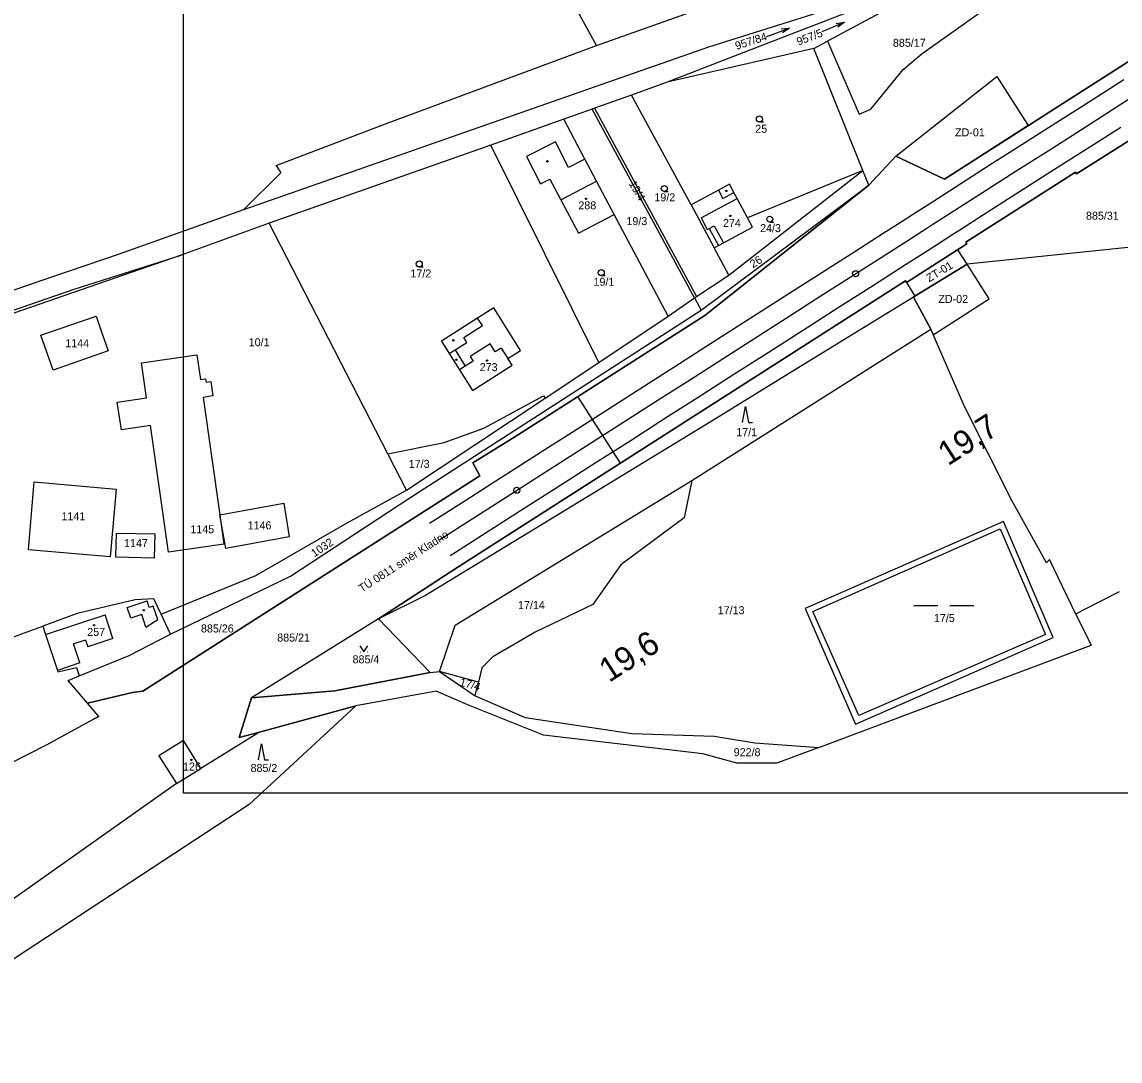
# Model space of a CAD drawing. Extents: x -752184 to -751416, y -1028299 to -1027836.
# Drawn here: x -751921.2 to -751646.8, y -1028255.6 to -1027995.9 of the extents above; entities that cross this region are included whole.
import ezdxf

# ---------------------------------------------------------------- set-up
doc = ezdxf.new("R2010")
doc.units = 0
for name, color, linetype in [('02_Osa_koleje', 7, 'Continuous'), ('03_Staničení', 7, 'Continuous'), ('Dočasné zábory', 7, 'Continuous'), ('Dočasné zábory - čísla', 7, 'Continuous'), ('Pozemky ČD', 7, 'Continuous'), ('Trvalé zábory', 7, 'Continuous'), ('Trvalé zábory - čísla', 7, 'Continuous'), ('Vrstva 4', 7, 'Continuous'), ('Vrstva 53', 7, 'Continuous'), ('Vrstva 55', 7, 'Continuous'), ('Vrstva 56', 7, 'Continuous'), ('Vrstva 57', 7, 'Continuous'), ('Vrstva 58', 7, 'Continuous'), ('Vrstva 59', 7, 'Continuous')]:
    doc.layers.add(name, color=color, linetype=linetype)

msp = doc.modelspace()

# ---------------------------------------------------------------- linework, layer by layer
at = {"layer": '02_Osa_koleje'}
for p, q in [((-751653.82, -1028015.29), (-751645.91, -1028010.23)), ((-751648.69, -1028017.73), (-751640.92, -1028012.76)), ((-751662.87, -1028021.07), (-751653.82, -1028015.29)), ((-751656.74, -1028022.88), (-751648.69, -1028017.73)), ((-751671.32, -1028026.46), (-751662.87, -1028021.07)), ((-751664.8, -1028028.03), (-751656.74, -1028022.88)), ((-751655.05, -1028027.47), (-751646.64, -1028022.11)), ((-751679.23, -1028031.51), (-751671.32, -1028026.46)), ((-751663.19, -1028032.68), (-751655.05, -1028027.47)), ((-751673, -1028033.27), (-751664.8, -1028028.03)), ((-751686.59, -1028036.23), (-751679.23, -1028031.51)), ((-751671.92, -1028038.25), (-751663.19, -1028032.68)), ((-751681.21, -1028038.52), (-751673, -1028033.27)), ((-751693.69, -1028040.78), (-751686.59, -1028036.23)), ((-751688.98, -1028043.49), (-751681.21, -1028038.52)), ((-751680.91, -1028044.01), (-751671.92, -1028038.25)), ((-751697.47, -1028043.2), (-751693.69, -1028040.78)), ((-751702.42, -1028046.37), (-751697.47, -1028043.2)), ((-751691.1, -1028044.85), (-751688.98, -1028043.49)), ((-751686.82, -1028047.78), (-751680.91, -1028044.01)), ((-751705.97, -1028048.65), (-751702.42, -1028046.37)), ((-751695.1, -1028047.41), (-751693.57, -1028046.42)), ((-751693.57, -1028046.42), (-751691.1, -1028044.85)), ((-751713.11, -1028053.22), (-751705.97, -1028048.65)), ((-751699.61, -1028050.29), (-751697.44, -1028048.9)), ((-751697.44, -1028048.9), (-751695.1, -1028047.41)), ((-751692.69, -1028051.52), (-751688.81, -1028049.05)), ((-751688.81, -1028049.05), (-751686.82, -1028047.78)), ((-751707.41, -1028055.27), (-751699.61, -1028050.29)), ((-751696.88, -1028054.2), (-751692.69, -1028051.52)), ((-751722.23, -1028059.04), (-751713.11, -1028053.22)), ((-751700.46, -1028056.5), (-751696.88, -1028054.2)), ((-751715.15, -1028060.22), (-751707.41, -1028055.27)), ((-751708.45, -1028061.62), (-751700.46, -1028056.5)), ((-751731.44, -1028064.93), (-751722.23, -1028059.04)), ((-751722.91, -1028065.18), (-751715.15, -1028060.22)), ((-751717.26, -1028067.26), (-751708.45, -1028061.62)), ((-751740.37, -1028070.64), (-751731.44, -1028064.93)), ((-751730.24, -1028069.87), (-751722.91, -1028065.18)), ((-751726.12, -1028072.93), (-751717.26, -1028067.26)), ((-751749.1, -1028076.23), (-751740.37, -1028070.64)), ((-751738.35, -1028075.06), (-751730.24, -1028069.87)), ((-751734.76, -1028078.44), (-751726.12, -1028072.93)), ((-751758.04, -1028081.94), (-751749.1, -1028076.23)), ((-751746.01, -1028079.96), (-751738.35, -1028075.06)), ((-751743.32, -1028083.91), (-751734.76, -1028078.44)), ((-751767.69, -1028088.11), (-751758.04, -1028081.94)), ((-751754.17, -1028085.18), (-751746.01, -1028079.96)), ((-751762.21, -1028090.32), (-751754.17, -1028085.18)), ((-751752.24, -1028089.62), (-751743.32, -1028083.91)), ((-751776.82, -1028093.96), (-751767.69, -1028088.11)), ((-751769.91, -1028095.24), (-751762.21, -1028090.32)), ((-751759.86, -1028094.49), (-751752.24, -1028089.62)), ((-751785.51, -1028099.52), (-751776.82, -1028093.96)), ((-751777.26, -1028099.94), (-751769.91, -1028095.24)), ((-751769.24, -1028100.51), (-751759.86, -1028094.49)), ((-751795.35, -1028105.81), (-751788.71, -1028101.56)), ((-751788.71, -1028101.56), (-751785.51, -1028099.52)), ((-751785.09, -1028104.95), (-751777.26, -1028099.94)), ((-751777.92, -1028106.05), (-751769.24, -1028100.51)), ((-751803.67, -1028111.13), (-751796.99, -1028106.86)), ((-751796.99, -1028106.86), (-751795.35, -1028105.81)), ((-751793.41, -1028110.27), (-751785.09, -1028104.95)), ((-751787.91, -1028112.43), (-751777.92, -1028106.05)), ((-751807.69, -1028113.7), (-751803.67, -1028111.13)), ((-751801.11, -1028115.2), (-751793.41, -1028110.27)), ((-751797.49, -1028118.58), (-751787.91, -1028112.43)), ((-751818.04, -1028120.32), (-751810.27, -1028115.34)), ((-751810.27, -1028115.35), (-751807.69, -1028113.7)), ((-751808.72, -1028120.07), (-751801.11, -1028115.2)), ((-751819.33, -1028121.15), (-751818.04, -1028120.32)), ((-751816.72, -1028125.18), (-751808.72, -1028120.07)), ((-751806.31, -1028124.21), (-751797.49, -1028118.58)), ((-751816.74, -1028125.19), (-751816.72, -1028125.18)), ((-751812.84, -1028128.4), (-751806.31, -1028124.21)), ((-751814.16, -1028129.24), (-751812.84, -1028128.4))]:
    msp.add_line(p, q, dxfattribs=at)
at = {"layer": '03_Staničení'}
for centre in [(-751712.88, -1028058.77), (-751797.54, -1028112.91)]:
    msp.add_circle(centre, 0.75, dxfattribs=at)
at = {"layer": 'Dočasné zábory'}
for points in [[(-751669.8, -1028021.76), (-751690.7, -1028035.11), (-751702.85, -1028029.39), (-751677.63, -1028009.51)], [(-751698.4, -1028064.61), (-751694.07, -1028072.66), (-751693.47, -1028074.05), (-751679.48, -1028065.03), (-751685.04, -1028056.42), (-751698.06, -1028064.4)]]:
    msp.add_lwpolyline(points, close=True, dxfattribs=at)
at = {"layer": 'Pozemky ČD'}
msp.add_lwpolyline([(-751644.14, -1028025.2), (-751657.66, -1028033.82), (-751657.93, -1028033.4), (-751685.36, -1028050.92), (-751685.1, -1028051.35), (-751700.15, -1028061), (-751700.39, -1028060.59), (-751771.59, -1028106.11), (-751782.26, -1028089.44), (-751750.57, -1028069.21), (-751709.61, -1028036.63), (-751702.85, -1028029.39), (-751690.7, -1028035.11), (-751669.8, -1028021.76), (-751634.83, -1027999.42)], dxfattribs=at)
at = {"layer": 'Trvalé zábory'}
msp.add_lwpolyline([(-751700.15, -1028061), (-751698.06, -1028064.4), (-751685.04, -1028056.42), (-751687.36, -1028052.8)], close=True, dxfattribs=at)
at = {"layer": 'Vrstva 4'}
msp.add_lwpolyline([(-751880.79, -1027897.6), (-751466.79, -1027897.6), (-751466.79, -1028188.6), (-751880.79, -1028188.6)], close=True, dxfattribs=at)
at = {"layer": 'Vrstva 53'}
for points in [[(-751934.1, -1028186.19), (-751914.9, -1028176.41), (-751903.43, -1028170.23), (-751901.96, -1028169.44), (-751904.77, -1028166.14), (-751893.52, -1028163.47), (-751890.97, -1028163.13), (-751806.75, -1028109.29), (-751808.53, -1028106.05), (-751798.29, -1028099.68), (-751750.57, -1028069.21), (-751709.61, -1028036.63), (-751702.85, -1028029.39), (-751690.7, -1028035.11), (-751634.83, -1027999.42), (-751532.07, -1027933.64), (-751519.82, -1027926.47), (-751506.87, -1027919.58), (-751494.13, -1027913.25), (-751481.54, -1027906.54), (-751469.19, -1027899.14), (-751466.79, -1027897.6)], [(-751644.14, -1028025.2), (-751657.66, -1028033.82), (-751657.93, -1028033.4), (-751685.36, -1028050.92), (-751685.1, -1028051.35), (-751700.15, -1028061), (-751700.39, -1028060.59), (-751811.98, -1028131.93), (-751832.08, -1028145), (-751819.17, -1028158.43), (-751842.96, -1028162.99), (-751863.83, -1028164.81), (-751866.87, -1028174.68), (-751861.84, -1028173.32), (-751837.73, -1028166.78), (-751864.36, -1028191.47), (-751928.16, -1028233.3)]]:
    msp.add_lwpolyline(points, dxfattribs=at)
at = {"layer": 'Vrstva 55'}
for p, q in [((-751777.61, -1028001.77), (-751795.36, -1027969.33)), ((-751777.61, -1028001.77), (-751721.34, -1027981.66)), ((-751684.34, -1027981.6), (-751719.87, -1028000.62)), ((-751830.33, -1028021.31), (-751777.61, -1028001.77)), ((-751723.32, -1028002.47), (-751759.96, -1028010.88)), ((-751723.32, -1028002.47), (-751719.87, -1028000.62)), ((-751711.11, -1028032.94), (-751723.32, -1028002.47)), ((-751759.96, -1028010.88), (-751768.84, -1028014.13)), ((-751768.84, -1028014.13), (-751778.12, -1028017.44)), ((-751754, -1028041.6), (-751768.84, -1028014.13)), ((-751778.69, -1028017.64), (-751785.81, -1028020.18)), ((-751778.12, -1028017.44), (-751778.69, -1028017.64)), ((-751753.17, -1028064.84), (-751778.69, -1028017.64)), ((-751778.12, -1028017.44), (-751752.67, -1028064.5)), ((-751857.65, -1028031.73), (-751830.33, -1028021.31)), ((-751785.81, -1028020.18), (-751803.99, -1028026.65)), ((-751780.53, -1028030.11), (-751785.81, -1028020.18)), ((-751803.99, -1028026.65), (-751859.41, -1028046.14)), ((-751777.01, -1028080.95), (-751803.99, -1028026.65)), ((-751780.53, -1028030.11), (-751784.62, -1028032.2)), ((-751702.85, -1028029.39), (-751709.61, -1028036.63)), ((-751744.55, -1028059.1), (-751711.11, -1028032.94)), ((-751711.11, -1028032.94), (-751739.87, -1028044.82)), ((-751709.61, -1028036.63), (-751711.11, -1028032.94)), ((-751751.51, -1028067.92), (-751709.61, -1028036.63)), ((-751709.61, -1028036.63), (-751750.57, -1028069.21)), ((-751895.64, -1028053.38), (-751865.7, -1028042.71)), ((-751759.72, -1028069.4), (-751773.17, -1028043.99)), ((-751754, -1028041.6), (-751748.2, -1028052.33)), ((-751859.41, -1028046.14), (-751881.38, -1028054.14)), ((-751829.79, -1028103.79), (-751859.41, -1028046.14)), ((-751881.38, -1028054.14), (-752003.38, -1028096.4)), ((-751896.64, -1028053.77), (-751913.74, -1028059.67)), ((-751895.64, -1028053.38), (-751896.64, -1028053.77)), ((-751744.55, -1028059.1), (-751748.2, -1028052.33)), ((-751913.74, -1028059.67), (-751933.45, -1028066.43)), ((-751752.67, -1028064.5), (-751744.55, -1028059.1)), ((-751759.72, -1028069.4), (-751753.17, -1028064.84)), ((-751753.17, -1028064.84), (-751752.67, -1028064.5)), ((-751753.17, -1028064.84), (-751751.51, -1028067.92)), ((-751694.07, -1028072.66), (-751698.4, -1028064.61)), ((-751777.01, -1028080.95), (-751759.72, -1028069.4)), ((-751753.83, -1028110.42), (-751694.07, -1028072.66)), ((-751790.46, -1028089.89), (-751777.01, -1028080.95)), ((-751825.11, -1028112.91), (-751790.46, -1028089.89)), ((-751825.11, -1028112.91), (-751829.79, -1028103.79)), ((-751832.08, -1028145), (-751811.98, -1028131.93)), ((-751884.03, -1028148.84), (-751886.38, -1028143.87)), ((-751832.08, -1028145), (-751863.83, -1028164.81)), ((-751832.08, -1028145), (-751819.17, -1028158.43)), ((-751657.84, -1028143.83), (-751654.06, -1028151.61)), ((-751722.1, -1028177.18), (-751654.06, -1028151.61)), ((-751819.17, -1028158.43), (-751816.81, -1028158.16)), ((-751807.12, -1028160.84), (-751816.81, -1028158.16)), ((-751816.81, -1028158.16), (-751807.94, -1028164.26)), ((-751909.62, -1028160.48), (-751906.85, -1028159.28)), ((-751904.77, -1028166.14), (-751909.62, -1028160.48)), ((-751807.94, -1028164.26), (-751807.12, -1028160.84)), ((-751893.52, -1028163.47), (-751904.77, -1028166.14)), ((-751901.96, -1028169.44), (-751904.77, -1028166.14)), ((-751837.73, -1028166.78), (-751861.84, -1028173.32)), ((-751901.96, -1028169.44), (-751903.43, -1028170.23)), ((-751861.84, -1028173.32), (-751876.44, -1028182.41)), ((-751722.1, -1028177.18), (-751732.54, -1028181.1)), ((-751732.54, -1028181.1), (-751742.53, -1028181.08)), ((-751882.55, -1028186.22), (-751876.44, -1028182.41)), ((-751882.55, -1028186.22), (-751980.73, -1028255.56))]:
    msp.add_line(p, q, dxfattribs=at)
for points in [[(-751469.19, -1027899.14), (-751481.54, -1027906.54), (-751494.13, -1027913.25), (-751506.87, -1027919.58), (-751519.82, -1027926.47), (-751532.07, -1027933.64), (-751634.83, -1027999.42), (-751690.7, -1028035.11), (-751702.85, -1028029.39)], [(-751865.7, -1028042.71), (-751749.56, -1028002.08), (-751713.49, -1027990.7), (-751668.79, -1027968.97)], [(-751684.34, -1027981.6), (-751721.79, -1027996.16), (-751725.3, -1027997.51), (-751759.96, -1028010.88)], [(-751719.87, -1028000.62), (-751712.01, -1028018.94), (-751709.09, -1028017.63), (-751700.97, -1028007.7), (-751696.27, -1028003.7), (-751679.08, -1027991.59)], [(-751811.98, -1028131.93), (-751700.39, -1028060.59), (-751700.15, -1028061), (-751685.1, -1028051.35), (-751685.36, -1028050.92), (-751657.93, -1028033.4), (-751657.66, -1028033.82), (-751644.14, -1028025.2)], [(-751784.62, -1028032.2), (-751787.87, -1028025.82), (-751795.1, -1028029.46), (-751791.61, -1028036.31), (-751789.26, -1028035.12), (-751786.51, -1028040.34)], [(-751597.31, -1028027.06), (-751634.36, -1028051.12), (-751685.04, -1028056.42), (-751698.4, -1028064.61)], [(-751773.17, -1028043.99), (-751777.58, -1028035.66), (-751780.53, -1028030.11)], [(-751857.65, -1028031.73), (-751856.49, -1028033.54), (-751865.7, -1028042.71)], [(-751739.87, -1028044.82), (-751742.48, -1028039.98), (-751743.32, -1028038.44), (-751744.41, -1028036.42), (-751747.18, -1028037.91), (-751754, -1028041.6)], [(-751786.51, -1028040.34), (-751782.14, -1028048.67), (-751773.17, -1028043.99)], [(-751748.2, -1028052.33), (-751747.12, -1028051.75), (-751745.92, -1028051.1), (-751738.61, -1028047.15), (-751739.87, -1028044.82)], [(-752003.56, -1028095.62), (-751908.15, -1028062.63), (-751881.38, -1028054.14)], [(-751698.4, -1028064.61), (-751729.61, -1028083.77), (-751749, -1028095.68), (-751820.32, -1028139.23), (-751832.08, -1028145)], [(-751884.03, -1028148.84), (-751854.09, -1028134.41), (-751824.25, -1028114.78), (-751751.51, -1028067.92)], [(-751807.31, -1028069.85), (-751816.38, -1028075.6), (-751814.4, -1028078.72), (-751811.83, -1028082.78), (-751808.57, -1028087.93), (-751798.69, -1028081.67), (-751799.78, -1028079.96), (-751796.57, -1028077.93), (-751803.3, -1028067.31), (-751807.31, -1028069.85)], [(-751902.66, -1028069.39), (-751901.2, -1028073.54), (-751899.62, -1028078.07), (-751913.4, -1028082.89), (-751916.47, -1028074.11), (-751911.88, -1028072.54), (-751902.66, -1028069.39)], [(-751750.57, -1028069.21), (-751798.29, -1028099.68), (-751808.53, -1028106.05), (-751806.75, -1028109.29), (-751890.97, -1028163.13), (-751893.52, -1028163.47)], [(-751657.84, -1028143.83), (-751664.47, -1028130.17), (-751665.22, -1028131.05), (-751673.89, -1028115.42), (-751685.71, -1028091.93), (-751694.07, -1028072.66)], [(-751871.76, -1028119), (-751870.71, -1028126.36), (-751884.51, -1028128.34), (-751889.05, -1028096.75), (-751896.33, -1028097.8), (-751897.36, -1028090.88), (-751890.04, -1028089.83), (-751891.29, -1028081.06), (-751877.43, -1028079.08), (-751876.57, -1028085.19), (-751875.28, -1028085.01), (-751875.15, -1028085.9), (-751873.96, -1028085.73), (-751873.45, -1028089.34), (-751875.93, -1028089.7), (-751871.76, -1028119)], [(-751829.79, -1028103.79), (-751815.64, -1028100.96), (-751805.78, -1028097.41), (-751790.88, -1028089.26), (-751790.46, -1028089.89)], [(-751897.63, -1028112.6), (-751899.12, -1028129.53), (-751919.55, -1028127.76), (-751918.08, -1028110.8), (-751897.63, -1028112.6)], [(-751816.81, -1028158.16), (-751812.9, -1028146.59), (-751753.83, -1028110.42)], [(-751753.83, -1028110.42), (-751755.69, -1028119.78), (-751771.54, -1028131.54), (-751778.55, -1028141.46), (-751792.98, -1028148.4), (-751803.51, -1028154.54), (-751806.26, -1028157.26), (-751807.12, -1028160.84)], [(-751886.38, -1028143.87), (-751862.7, -1028134.19), (-751839.92, -1028121.01), (-751825.11, -1028112.91)], [(-751871.76, -1028119), (-751855.74, -1028116.09), (-751854.37, -1028124.51), (-751870.23, -1028127.46), (-751871.76, -1028119)], [(-751663.5, -1028149.71), (-751675.94, -1028120.67), (-751725.5, -1028142.46), (-751712.88, -1028171.35), (-751663.5, -1028149.71)], [(-751897.58, -1028123.64), (-751887.96, -1028123.82), (-751888.1, -1028129.87), (-751897.72, -1028129.64), (-751897.58, -1028123.64)], [(-751886.38, -1028143.87), (-751888.21, -1028140.02), (-751892.91, -1028140.3), (-751907.34, -1028143.68), (-751915.97, -1028146.83)], [(-751647, -1028138.31), (-751656, -1028142.89), (-751657.84, -1028143.83)], [(-751948.62, -1028160.91), (-751948.85, -1028157.62), (-751925.12, -1028150.18), (-751915.97, -1028146.83)], [(-751915.97, -1028146.83), (-751915.28, -1028148.92), (-751912.32, -1028157.92), (-751912.2, -1028158.29)], [(-751906.85, -1028159.28), (-751894.37, -1028154.17), (-751884.03, -1028148.84)], [(-751912.2, -1028158.29), (-751907.54, -1028157.19), (-751906.85, -1028159.28)], [(-751863.83, -1028164.81), (-751842.96, -1028162.99), (-751819.17, -1028158.43)], [(-751742.53, -1028181.08), (-751751.04, -1028178.81), (-751790.89, -1028174.07), (-751809.18, -1028166.74), (-751817.68, -1028163.14), (-751837.73, -1028166.78)], [(-751807.94, -1028164.26), (-751795.47, -1028169.71), (-751768.76, -1028173.66), (-751748.19, -1028174.34), (-751738.05, -1028176.01), (-751722.1, -1028177.18)], [(-751837.73, -1028166.78), (-751864.36, -1028191.47), (-751928.16, -1028233.3), (-751967.27, -1028248.1), (-751980.73, -1028255.56)], [(-751861.84, -1028173.32), (-751866.87, -1028174.68), (-751863.83, -1028164.81)], [(-752025.93, -1028240.15), (-751982.6, -1028213.59), (-751934.1, -1028186.19), (-751914.9, -1028176.41), (-751903.43, -1028170.23)], [(-751876.44, -1028182.41), (-751880.8, -1028175.41), (-751886.93, -1028179.3), (-751882.55, -1028186.22)]]:
    msp.add_lwpolyline(points, dxfattribs=at)
at = {"layer": 'Vrstva 56'}
for p, q in [((-751786.51, -1028040.34), (-751777.58, -1028035.66)), ((-751747.18, -1028037.91), (-751746.09, -1028039.94)), ((-751746.09, -1028039.94), (-751743.32, -1028038.44)), ((-751751.47, -1028044.84), (-751742.48, -1028039.98)), ((-751751.47, -1028044.84), (-751749.93, -1028047.7)), ((-751749.93, -1028047.7), (-751749.45, -1028047.44)), ((-751749.45, -1028047.44), (-751748.25, -1028046.79)), ((-751749.45, -1028047.44), (-751747.12, -1028051.75)), ((-751748.25, -1028046.79), (-751745.92, -1028051.1)), ((-751806.11, -1028071.75), (-751807.31, -1028069.85)), ((-751810.79, -1028074.72), (-751806.11, -1028071.75)), ((-751812.97, -1028077.81), (-751810.02, -1028075.95)), ((-751810.02, -1028075.95), (-751810.79, -1028074.72)), ((-751804.21, -1028076.3), (-751809.16, -1028079.43)), ((-751802.93, -1028078.33), (-751804.21, -1028076.3)), ((-751814.4, -1028078.72), (-751812.97, -1028077.81)), ((-751812.97, -1028077.81), (-751810.4, -1028081.87)), ((-751809.16, -1028079.43), (-751808.41, -1028080.61)), ((-751801.41, -1028077.37), (-751802.93, -1028078.33)), ((-751801.41, -1028077.37), (-751799.78, -1028079.96)), ((-751810.4, -1028081.87), (-751811.83, -1028082.78)), ((-751808.41, -1028080.61), (-751810.4, -1028081.87)), ((-751723.57, -1028143.22), (-751676.75, -1028122.56)), ((-751676.75, -1028122.56), (-751665.43, -1028148.92)), ((-751894.85, -1028142.2), (-751889.87, -1028140.56)), ((-751893.98, -1028144.86), (-751894.85, -1028142.2)), ((-751889.34, -1028142.18), (-751889.87, -1028140.56)), ((-751888.34, -1028141.85), (-751889.34, -1028142.18)), ((-751887.25, -1028145.18), (-751888.34, -1028141.85)), ((-751915.28, -1028148.92), (-751900.38, -1028144.02)), ((-751898.43, -1028149.96), (-751900.38, -1028144.02)), ((-751891.22, -1028143.96), (-751893.98, -1028144.86)), ((-751890.18, -1028147.14), (-751891.22, -1028143.96)), ((-751890.18, -1028147.14), (-751887.25, -1028145.18)), ((-751712.04, -1028169.17), (-751723.57, -1028143.22)), ((-751905.3, -1028150.34), (-751908.27, -1028151.31)), ((-751905.3, -1028150.34), (-751904.74, -1028152.04)), ((-751898.43, -1028149.96), (-751904.74, -1028152.04)), ((-751665.43, -1028148.92), (-751712.04, -1028169.17)), ((-751906.7, -1028156.07), (-751908.27, -1028151.31)), ((-751906.7, -1028156.07), (-751912.32, -1028157.92))]:
    msp.add_line(p, q, dxfattribs=at)
at = {"layer": 'Vrstva 58'}
for p, q in [((-751735.07, -1027999.45), (-751729.44, -1027997.38)), ((-751721.24, -1027998.21), (-751715.7, -1027995.9)), ((-751736.92, -1028020.84), (-751735.92, -1028020.84)), ((-751760.69, -1028038.22), (-751759.69, -1028038.22)), ((-751734.32, -1028045.89), (-751733.32, -1028045.89)), ((-751821.89, -1028057.08), (-751820.89, -1028057.08)), ((-751776.42, -1028059.25), (-751775.42, -1028059.25)), ((-751698.31, -1028141.68), (-751692.31, -1028141.68)), ((-751689.31, -1028141.68), (-751683.31, -1028141.68)), ((-751836.66, -1028153.26), (-751836.56, -1028153.26)), ((-751834.86, -1028153.26), (-751834.76, -1028153.26))]:
    msp.add_line(p, q, dxfattribs=at)
for points in [[(-751731.49, -1027997.61), (-751729.44, -1027997.38), (-751731.14, -1027998.54)], [(-751717.74, -1027996.21), (-751715.7, -1027995.9), (-751717.36, -1027997.13)], [(-751741.12, -1028095.98), (-751740.37, -1028091.98), (-751739.62, -1028095.98), (-751738.62, -1028095.98)], [(-751836.71, -1028151.76), (-751835.71, -1028153.26), (-751834.71, -1028151.76)], [(-751862.07, -1028180.28), (-751861.32, -1028176.28), (-751860.57, -1028180.28), (-751859.57, -1028180.28)]]:
    msp.add_lwpolyline(points, dxfattribs=at)
for centre in [(-751736.92, -1028020.09), (-751760.69, -1028037.47), (-751734.32, -1028045.14), (-751821.89, -1028056.33), (-751776.42, -1028058.5)]:
    msp.add_circle(centre, 0.75, dxfattribs=at)
at = {"layer": 'Vrstva 59'}
for centre in [(-751789.9, -1028030.69), (-751745.22, -1028038.07), (-751780.23, -1028040.05), (-751744.16, -1028044.32), (-751813.36, -1028075.42), (-751812.67, -1028080.3), (-751804.96, -1028080.47), (-751890.74, -1028142.88), (-751903.15, -1028146.63), (-751878.83, -1028180.29)]:
    msp.add_circle(centre, 0.175, dxfattribs=at)

# ---------------------------------------------------------------- texts
at = {"layer": '02_Osa_koleje'}
msp.add_text('TÚ 0811 směr Kladno', height=2, rotation=32.6028, dxfattribs=at).set_placement((-751836.27, -1028138.5))
at = {"layer": '03_Staničení'}
for s, rotation, p in [('19,7', 32.5978, (-751689.82, -1028106.93)), ('19,6', 32.6004, (-751774.48, -1028161.08))]:
    msp.add_text(s, height=6, rotation=rotation, dxfattribs=at).set_placement(p)
at = {"layer": 'Dočasné zábory - čísla'}
for s, p in [('ZD-01', (-751688.04, -1028024.44)), ('ZD-02', (-751692.21, -1028066.08))]:
    msp.add_text(s, height=2, dxfattribs=at).set_placement(p)
at = {"layer": 'Trvalé zábory - čísla'}
msp.add_text('ZT-01', height=2, rotation=30.8056, dxfattribs=at).set_placement((-751694.5, -1028060.92))
at = {"layer": 'Vrstva 57'}
for s, rotation, p in [('957/84', 18, (-751742.62, -1028002.85)), ('957/5', 21, (-751727.16, -1028001.77)), ('19/4', 299.3436, (-751769.61, -1028036.25)), ('26', 33, (-751738.49, -1028057.43)), ('1032', 34, (-751848.08, -1028129.69)), ('17/4', 345, (-751811.96, -1028161.71))]:
    msp.add_text(s, height=2, rotation=rotation, dxfattribs=at).set_placement(p)
for s, p in [('885/17', (-751703.56, -1028002.07)), ('25', (-751737.96, -1028023.55)), ('288', (-751782.15, -1028042.69)), ('19/2', (-751763.16, -1028040.68)), ('885/31', (-751655.33, -1028045.28)), ('19/3', (-751770.14, -1028046.63)), ('274', (-751746.02, -1028047.07)), ('24/3', (-751736.75, -1028048.38)), ('17/2', (-751824.11, -1028059.72)), ('19/1', (-751778.37, -1028061.79)), ('1144', (-751910.34, -1028077.17)), ('10/1', (-751864.51, -1028076.89)), ('273', (-751806.8, -1028083.13)), ('17/1', (-751742.71, -1028099.38)), ('17/3', (-751824.52, -1028107.3)), ('1141', (-751911.28, -1028120.38)), ('1146', (-751864.79, -1028122.68)), ('1145', (-751879.09, -1028123.65)), ('1147', (-751895.65, -1028127.09)), ('17/14', (-751797.22, -1028142.59)), ('17/13', (-751747.33, -1028143.88)), ('17/5', (-751693.32, -1028145.84)), ('257', (-751904.85, -1028149.31)), ('885/26', (-751876.44, -1028148.44)), ('885/21', (-751857.39, -1028150.72)), ('885/4', (-751838.56, -1028156.15)), ('922/8', (-751743.34, -1028179.36)), ('126', (-751880.91, -1028182.95)), ('885/2', (-751864.05, -1028183.3))]:
    msp.add_text(s, height=2, dxfattribs=at).set_placement(p)

doc.saveas('drawing.dxf')
